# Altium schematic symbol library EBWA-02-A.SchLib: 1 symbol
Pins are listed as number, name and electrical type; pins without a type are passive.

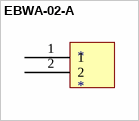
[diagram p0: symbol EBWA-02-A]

## EBWA-02-A
designator *
footprint EBWA-02-A
pins: 1, 2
